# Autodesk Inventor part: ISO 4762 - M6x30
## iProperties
Created: 2001-08
Part Number: ISO 4762 - M6x30
Catalog Web Link: file:///D:/Program%20Files/Autodesk/Inventor%205/Content/Iso/index.htm?doNavigateId=932883F9-F3A7-4770-8571-ED868C9DA26C|14B194F0CA4449A681017FB9C384CD9B|true
Description: Hexagon Socket Head Cap Screw
Document SubType Name: Standard Catalog Part
Standard: ISO 4762 - M6x30
Designer: Martin Budgell
Control State: 0
Master: False
Checked Out: False
Length Units: 11269
Angle Units: 11279
Time Units: 11290
Mass Units: 11283
Shininess: 3
Angle Display Precision: 2
Document Length Units: 11269
Document Angle Units: 11279
Document Time Units: 11290
Document Mass Units: 11283
Document Length Units Precision: 3
Document Angle Units Precision: 2
Compacted: True
CLASSIFICATION: 31161501 un/spsc
MANUFACTURER: ISO Standard System
Density: 0.0
Volumn: 0.0
Area: 0.0
PropertySet Name: Model Information
Author: Martin Budgell
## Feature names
1. Base1
